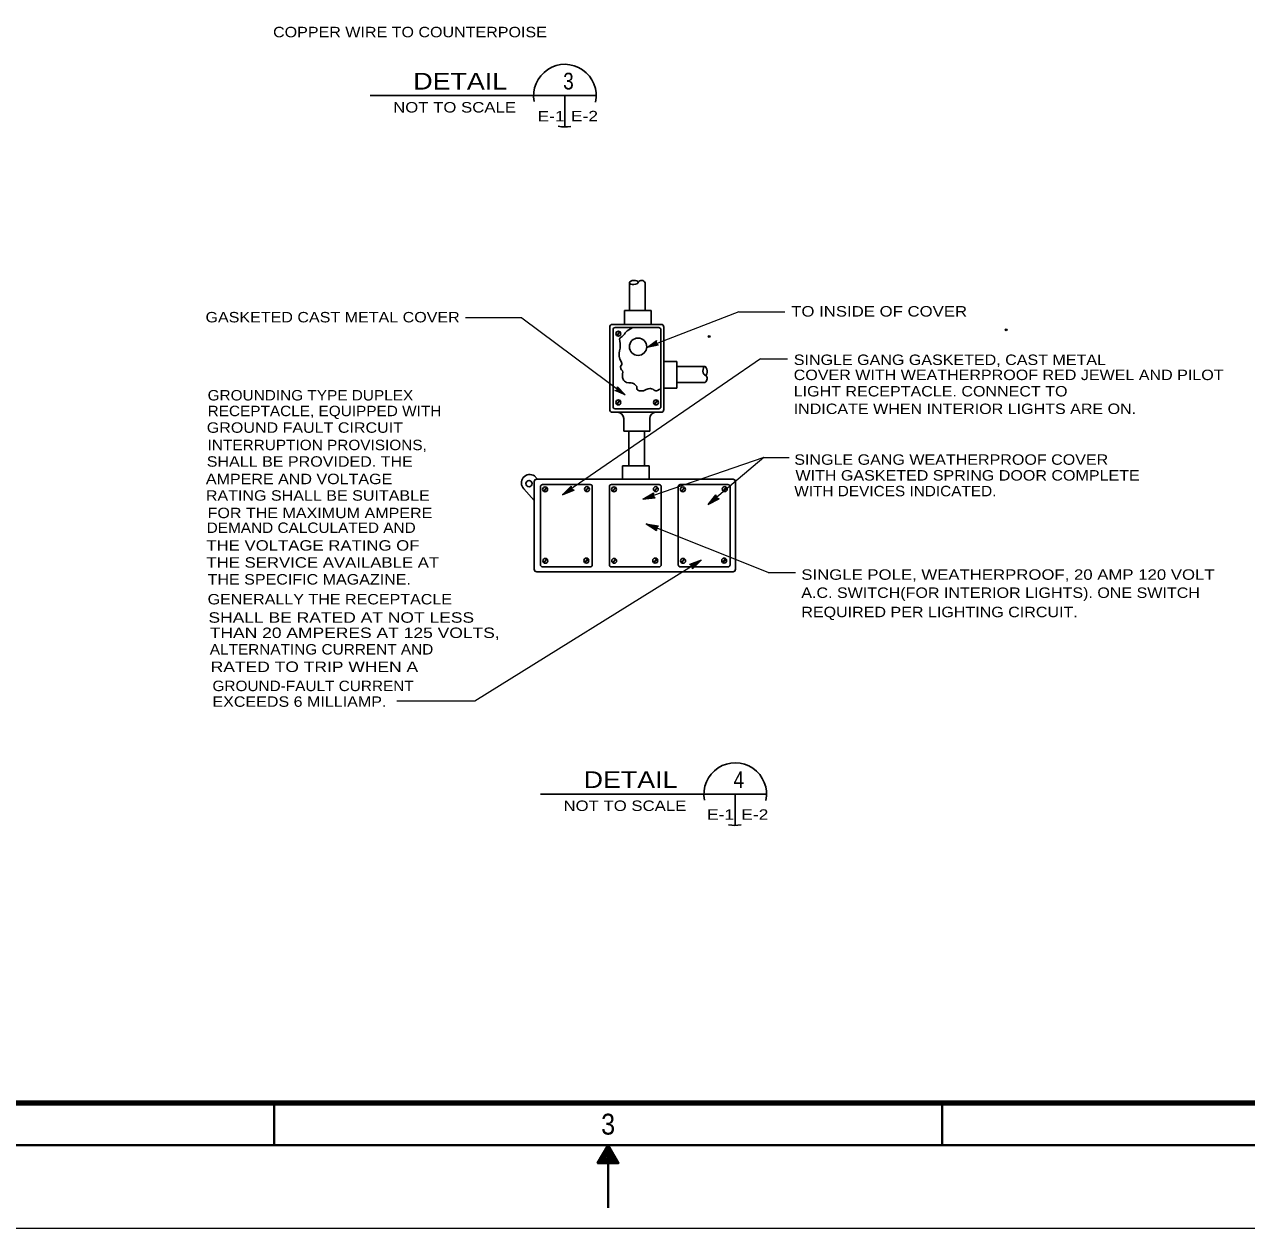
# Model space of a CAD drawing. Extents: x -39.6 to 16.1, y -17.6 to 34.
# Drawn here: x -11.89 to 2.75, y -17.59 to -3.17 of the extents above; entities that cross this region are included whole.
import ezdxf
from ezdxf.enums import TextEntityAlignment as Align

# ---------------------------------------------------------------- set-up
doc = ezdxf.new("R2010")
doc.units = 0
doc.header["$LTSCALE"] = 0.05
doc.header["$PDMODE"] = 32
doc.header["$PDSIZE"] = 0.025
doc.layers.add('1', color=7, linetype='Continuous', lineweight=13)

msp = doc.modelspace()

# ---------------------------------------------------------------- linework, layer by layer
at = {"layer": '1', "lineweight": 25}
for p, q in [((-7.74921, -4.02658), (-5.04021, -4.02658)), ((-5.41521, -4.02658), (-5.41521, -4.40158)), ((-4.64121, -6.60058), (-4.64121, -6.26658)), ((-4.45321, -6.60058), (-4.45321, -6.26658)), ((-4.70221, -6.76058), (-4.70221, -6.59958)), ((-4.38221, -6.59958), (-4.70221, -6.59958)), ((-4.38221, -6.76058), (-4.38221, -6.59958)), ((-4.87821, -6.80058), (-4.87821, -7.78258)), ((-4.26521, -6.76558), (-4.84321, -6.76558)), ((-4.83921, -6.82958), (-4.83921, -7.74958)), ((-4.29121, -6.80458), (-4.81421, -6.80458)), ((-4.75821, -6.85158), (-4.79821, -6.89558)), ((-4.75321, -6.85658), (-4.79321, -6.90058)), ((-4.26621, -6.82958), (-4.26621, -7.74958)), ((-4.23021, -6.80058), (-4.23021, -7.78258)), ((-4.23421, -7.21058), (-4.07321, -7.21058)), ((-4.07421, -7.27158), (-3.74021, -7.27158)), ((-4.07321, -7.53058), (-4.07321, -7.21058)), ((-4.07421, -7.45958), (-3.74021, -7.45958)), ((-4.23421, -7.53058), (-4.07321, -7.53058)), ((-4.75821, -7.67458), (-4.79821, -7.71858)), ((-4.75321, -7.67958), (-4.79321, -7.72358)), ((-4.30721, -7.67458), (-4.34721, -7.71858)), ((-4.30221, -7.67958), (-4.34221, -7.72358)), ((-4.26521, -7.81758), (-4.84321, -7.81758)), ((-4.29121, -7.77458), (-4.81421, -7.77458)), ((-4.71021, -7.89258), (-4.71021, -8.04258)), ((-4.39921, -7.89258), (-4.39921, -8.04258)), ((-4.39921, -8.04258), (-4.71021, -8.04258)), ((-4.65121, -8.45558), (-4.65121, -8.04258)), ((-4.46321, -8.45558), (-4.46321, -8.04258)), ((-4.72621, -8.61858), (-4.72621, -8.45758)), ((-4.72621, -8.45758), (-4.40621, -8.45758)), ((-4.72621, -8.61858), (-4.72621, -8.45758)), ((-4.40621, -8.45758), (-4.72621, -8.45758)), ((-4.40621, -8.61858), (-4.40621, -8.45758)), ((-4.40621, -8.61858), (-4.40621, -8.45758)), ((-5.74421, -8.61858), (-5.78621, -8.57258)), ((-5.75321, -8.61858), (-3.40221, -8.61858)), ((-5.78321, -8.87258), (-5.90821, -8.73458)), ((-5.78321, -9.69758), (-5.78321, -8.64858)), ((-5.70821, -9.64358), (-5.70821, -8.70858)), ((-5.68321, -8.68358), (-5.11221, -8.68358)), ((-5.67421, -8.76058), (-5.63421, -8.71658)), ((-5.66921, -8.76558), (-5.62921, -8.72158)), ((-5.17321, -8.75758), (-5.13321, -8.71358)), ((-5.16821, -8.76258), (-5.12821, -8.71858)), ((-5.08721, -9.64358), (-5.08721, -8.70858)), ((-4.88321, -9.64358), (-4.88321, -8.70858)), ((-4.85821, -8.68358), (-4.28721, -8.68358)), ((-4.84921, -8.76058), (-4.80921, -8.71658)), ((-4.84421, -8.76558), (-4.80421, -8.72158)), ((-4.34821, -8.75758), (-4.30821, -8.71358)), ((-4.34321, -8.76258), (-4.30321, -8.71858)), ((-4.26221, -9.64358), (-4.26221, -8.70858)), ((-4.05821, -9.64358), (-4.05821, -8.70858)), ((-4.03321, -8.68358), (-3.46221, -8.68358)), ((-4.02421, -8.76058), (-3.98421, -8.71658)), ((-4.01921, -8.76558), (-3.97921, -8.72158)), ((-3.52321, -8.75758), (-3.48321, -8.71358)), ((-3.51821, -8.76258), (-3.47821, -8.71858)), ((-3.43721, -9.64358), (-3.43721, -8.70858)), ((-3.37221, -9.69758), (-3.37221, -8.64858)), ((-5.67221, -9.61658), (-5.63221, -9.57258)), ((-5.66721, -9.62158), (-5.62721, -9.57758)), ((-5.18021, -9.61358), (-5.14021, -9.56958)), ((-5.17521, -9.61858), (-5.13521, -9.57458)), ((-4.84721, -9.61658), (-4.80721, -9.57258)), ((-4.84221, -9.62158), (-4.80221, -9.57758)), ((-4.35521, -9.61358), (-4.31521, -9.56958)), ((-4.35021, -9.61858), (-4.31021, -9.57458)), ((-4.02221, -9.61658), (-3.98221, -9.57258)), ((-4.01721, -9.62158), (-3.97721, -9.57758)), ((-3.53021, -9.61358), (-3.49021, -9.56958)), ((-3.52521, -9.61858), (-3.48521, -9.57458)), ((-5.75321, -9.72758), (-3.40221, -9.72758)), ((-5.68321, -9.66858), (-5.11221, -9.66858)), ((-4.85821, -9.66858), (-4.28721, -9.66858)), ((-4.03321, -9.66858), (-3.46221, -9.66858)), ((-5.70921, -12.38958), (-3.00021, -12.38958)), ((-3.37521, -12.38958), (-3.37521, -12.76458))]:
    msp.add_line(p, q, dxfattribs=at)
at = {"layer": '1'}
for p, q in [((-5.93021, -6.68658), (-6.60421, -6.68658)), ((-3.33221, -6.61658), (-4.42521, -7.03858)), ((-3.33221, -6.61658), (-2.78021, -6.61658)), ((-0.13521, -6.83258), (-0.13021, -6.83058)), ((-0.13521, -6.83258), (-0.13021, -6.83258)), ((-0.13421, -6.83258), (-0.13121, -6.83058)), ((-0.13421, -6.83258), (-0.13021, -6.83158)), ((-4.42521, -7.03858), (-4.31821, -6.95858)), ((-4.42521, -7.03858), (-4.29521, -7.01058)), ((-4.39821, -7.02658), (-4.32621, -6.97758)), ((-4.39821, -7.02658), (-4.31421, -7.00458)), ((-3.69121, -6.91058), (-3.68621, -6.90858)), ((-3.69121, -6.91058), (-3.68621, -6.91058)), ((-3.69021, -6.91058), (-3.68721, -6.90858)), ((-3.69021, -6.91058), (-3.68621, -6.90958)), ((-3.07221, -7.17958), (-5.44221, -8.80758)), ((-3.07221, -7.17958), (-2.74921, -7.17958)), ((-4.71921, -7.59258), (-4.79921, -7.55458)), ((-4.69421, -7.61058), (-4.78421, -7.51158)), ((-4.71921, -7.59258), (-4.78121, -7.53358)), ((-3.03121, -8.35858), (-4.48121, -8.85958)), ((-3.03121, -8.35858), (-3.69921, -8.92158)), ((-3.03121, -8.35858), (-2.72821, -8.35858)), ((-5.44221, -8.80758), (-5.34121, -8.70058)), ((-5.44221, -8.80758), (-5.30621, -8.75158)), ((-5.41221, -8.78658), (-5.34521, -8.71658)), ((-5.41221, -8.78658), (-5.32321, -8.74958)), ((-5.38221, -8.76658), (-5.35021, -8.73258)), ((-5.38221, -8.76658), (-5.34021, -8.74858)), ((-5.35021, -8.73258), (-5.34821, -8.74258)), ((-5.34821, -8.74258), (-5.34021, -8.74858)), ((-5.34521, -8.71658), (-5.34121, -8.73858)), ((-5.34121, -8.73858), (-5.32321, -8.74958)), ((-4.48121, -8.85958), (-4.35521, -8.78358)), ((-4.48121, -8.85958), (-4.33521, -8.84158)), ((-4.44621, -8.84758), (-4.36421, -8.79758)), ((-4.44621, -8.84758), (-4.35121, -8.83558)), ((-4.41221, -8.83558), (-4.37321, -8.81158)), ((-4.41221, -8.83558), (-4.36721, -8.82958)), ((-4.37321, -8.81158), (-4.37321, -8.82258)), ((-4.37321, -8.82258), (-4.36721, -8.82958)), ((-4.36421, -8.79758), (-4.36621, -8.81958)), ((-4.36621, -8.81958), (-4.35121, -8.83558)), ((-3.69921, -8.92158), (-3.60921, -8.80458)), ((-3.69921, -8.92158), (-3.56921, -8.85258)), ((-3.67121, -8.89758), (-3.61221, -8.82158)), ((-3.67121, -8.89758), (-3.58621, -8.85258)), ((-3.64321, -8.87458), (-3.61521, -8.83758)), ((-3.64321, -8.87458), (-3.60321, -8.85258)), ((-3.61521, -8.83758), (-3.61221, -8.84858)), ((-3.61221, -8.82158), (-3.60621, -8.84258)), ((-3.61221, -8.84858), (-3.60321, -8.85258)), ((-3.60621, -8.84258), (-3.58621, -8.85258)), ((-2.97921, -9.73558), (-4.44021, -9.15158)), ((-4.44021, -9.15158), (-4.29521, -9.17658)), ((-4.44021, -9.15158), (-4.31821, -9.23358)), ((-4.40621, -9.16558), (-4.31121, -9.18158)), ((-4.40621, -9.16558), (-4.32621, -9.21858)), ((-4.37221, -9.17858), (-4.33421, -9.20358)), ((-4.37221, -9.17858), (-4.32721, -9.18658)), ((-4.32721, -9.18658), (-4.33421, -9.19358)), ((-4.33421, -9.19358), (-4.33421, -9.20358)), ((-4.31121, -9.18158), (-4.32721, -9.19658)), ((-4.32721, -9.19658), (-4.32621, -9.21858)), ((-6.49221, -11.27458), (-3.78221, -9.58958)), ((-3.78221, -9.58958), (-3.92121, -9.63958)), ((-3.81321, -9.60958), (-3.90421, -9.64158)), ((-3.88621, -9.65358), (-3.90421, -9.64158)), ((-3.78221, -9.58958), (-3.88821, -9.69158)), ((-3.84421, -9.62858), (-3.88721, -9.64458)), ((-3.87921, -9.64958), (-3.88721, -9.64458)), ((-3.88321, -9.67558), (-3.88621, -9.65358)), ((-3.81321, -9.60958), (-3.88321, -9.67558)), ((-3.87721, -9.66058), (-3.87921, -9.64958)), ((-3.84421, -9.62858), (-3.87721, -9.66058)), ((-2.97921, -9.73558), (-2.65421, -9.73558)), ((-7.42821, -11.27458), (-6.49221, -11.27458)), ((16.10179, -17.59158), (-25.89821, -17.59158))]:
    msp.add_line(p, q, dxfattribs=at)
at = {"layer": '1', "lineweight": 40}
for p, q in [((-8.89821, -16.09158), (-8.89821, -16.59158)), ((-0.89821, -16.09158), (-0.89821, -16.59158)), ((-4.89821, -16.59158), (-4.89821, -17.34158))]:
    msp.add_line(p, q, dxfattribs=at)
for points in [[(-24.89821, -16.59158), (-24.89821, 11.40842), (15.10179, 11.40842), (15.10179, -16.59158)], [(-4.89821, -16.59158), (-4.77321, -16.80858), (-5.02321, -16.80858)]]:
    msp.add_lwpolyline(points, close=True, dxfattribs=at)
at = {"layer": '1', "lineweight": 90}
msp.add_lwpolyline([(-23.39821, 10.90842), (14.60179, 10.90842), (14.60179, -16.09158), (-23.39821, -16.09158)], close=True, dxfattribs=at)
at = {"layer": '1'}
for points in [[(-5.93021, -6.68658), (-4.69421, -7.61058), (-4.81721, -7.55658)], [(-0.13121, -6.83158), (-0.13221, -6.83158), (-0.13121, -6.83158)], [(-3.68721, -6.90958), (-3.68821, -6.90958), (-3.68721, -6.90958)], [(-5.34121, -8.70058), (-5.33521, -8.73358), (-5.30621, -8.75158)], [(-4.35521, -8.78358), (-4.35821, -8.81758), (-4.33521, -8.84158)], [(-3.60921, -8.80458), (-3.60021, -8.83758), (-3.56921, -8.85258)], [(-4.29521, -9.17658), (-4.31921, -9.19958), (-4.31821, -9.23358)], [(-3.88821, -9.69158), (-3.89221, -9.65858), (-3.92121, -9.63958)]]:
    msp.add_lwpolyline(points, dxfattribs=at)
at = {"layer": '1', "lineweight": 25}
msp.add_lwpolyline([(-4.26621, -7.54458), (-4.27721, -7.54158), (-4.28721, -7.54458), (-4.30621, -7.55558), (-4.31721, -7.55958), (-4.32721, -7.56058), (-4.33721, -7.55658), (-4.34621, -7.55358), (-4.35521, -7.54458), (-4.35921, -7.54458), (-4.36421, -7.54158), (-4.37721, -7.53558), (-4.38921, -7.53358), (-4.39921, -7.53358), (-4.41821, -7.53858), (-4.44021, -7.54558), (-4.45721, -7.55358), (-4.47321, -7.55958), (-4.49721, -7.56258), (-4.52021, -7.56058), (-4.53421, -7.55558), (-4.54421, -7.54858), (-4.54821, -7.54558), (-4.55221, -7.53158), (-4.55521, -7.50958), (-4.58221, -7.47958), (-4.59321, -7.47358), (-4.60421, -7.46958), (-4.62221, -7.46558), (-4.65121, -7.46458), (-4.67721, -7.46158), (-4.70221, -7.44458), (-4.71321, -7.43258), (-4.72621, -7.40058), (-4.72721, -7.37758), (-4.72421, -7.35558), (-4.72321, -7.33858), (-4.72621, -7.32258), (-4.73721, -7.30858), (-4.74421, -7.29858), (-4.74821, -7.26958), (-4.73521, -7.24458), (-4.73521, -7.23258), (-4.74121, -7.21158), (-4.75621, -7.18258), (-4.76721, -7.14558), (-4.76721, -7.10858), (-4.76321, -7.08258), (-4.75321, -7.05058), (-4.75221, -7.02958), (-4.75321, -6.99558), (-4.75921, -6.96758), (-4.76021, -6.94258), (-4.75321, -6.92758), (-4.73021, -6.90858), (-4.70221, -6.88058), (-4.69321, -6.86458), (-4.66821, -6.84458), (-4.62921, -6.81758), (-4.60321, -6.80458), (-4.60421, -6.80458)], dxfattribs=at)
at = {"layer": '1'}
for points in [[(-4.33421, -6.99858), (-4.33521, -7.00358), (-4.35921, -7.00958), (-4.33821, -6.99358)], [(-4.77621, -7.55458), (-4.77321, -7.54958), (-4.75421, -7.57058), (-4.77821, -7.55958)]]:
    msp.add_lwpolyline(points, close=True, dxfattribs=at)
at = {"layer": '1', "lineweight": 40}
for points in [[(-4.89721, -16.63458), (-4.80821, -16.78758), (-4.98621, -16.78758), (-4.89821, -16.63558)], [(-4.89821, -16.67358), (-4.84521, -16.76658), (-4.95021, -16.76658), (-4.89621, -16.67358)], [(-4.89821, -16.71658), (-4.88121, -16.74558), (-4.91421, -16.74558), (-4.89921, -16.71958)]]:
    msp.add_lwpolyline(points, dxfattribs=at)
at = {"layer": '1', "lineweight": 25}
for centre, radius in [((-4.77521, -6.87658), 0.02973), ((-4.53921, -7.03358), 0.10402), ((-4.77521, -7.69958), 0.02973), ((-4.32421, -7.69958), 0.02973), ((-5.84421, -8.67158), 0.03766), ((-5.65221, -8.74058), 0.02973), ((-5.15121, -8.73758), 0.02973), ((-4.82721, -8.74058), 0.02973), ((-4.32621, -8.73758), 0.02973), ((-4.00221, -8.74058), 0.02973), ((-3.50121, -8.73758), 0.02973), ((-5.65021, -9.59658), 0.02973), ((-5.15821, -9.59358), 0.02973), ((-4.82521, -9.59658), 0.02973), ((-4.33321, -9.59358), 0.02973), ((-4.00021, -9.59658), 0.02973), ((-3.50821, -9.59358), 0.02973)]:
    msp.add_circle(centre, radius, dxfattribs=at)
for centre, radius, start, end in [((-5.41521, -4.02658), 0.375, 348.02387, 190.92017), ((-5.41521, -4.02658), 0.375, 257.81974, 280.71312), ((-4.49786, -6.28722), 0.04919, 24.80309, 147.21509), ((-4.84321, -6.80058), 0.035, 90, 180), ((-4.81421, -6.82958), 0.025, 90, 180), ((-4.29121, -6.82958), 0.025, 0, 90), ((-4.26521, -6.80058), 0.035, 0, 90), ((-3.76084, -7.41493), 0.04919, 294.80309, 57.21509), ((-4.81421, -7.74958), 0.025, 180, 270), ((-4.29121, -7.74958), 0.025, 270, 0), ((-4.84321, -7.78258), 0.035, 180, 270), ((-4.78521, -7.89258), 0.075, 0, 90), ((-4.32421, -7.89258), 0.075, 90, 180), ((-4.26521, -7.78258), 0.035, 270, 0), ((-5.83597, -8.66406), 0.10095, 55.78574, 224.31098), ((-5.75321, -8.64858), 0.03, 90, 180), ((-3.40221, -8.64858), 0.03, 0, 90), ((-5.68321, -8.70858), 0.025, 90, 180), ((-5.11221, -8.70858), 0.025, 0, 90), ((-4.85821, -8.70858), 0.025, 90, 180), ((-4.28721, -8.70858), 0.025, 0, 90), ((-4.03321, -8.70858), 0.025, 90, 180), ((-3.46221, -8.70858), 0.025, 0, 90), ((-5.68321, -9.64358), 0.025, 180, 270), ((-5.11221, -9.64358), 0.025, 270, 0), ((-4.85821, -9.64358), 0.025, 180, 270), ((-4.28721, -9.64358), 0.025, 270, 0), ((-4.03321, -9.64358), 0.025, 180, 270), ((-3.46221, -9.64358), 0.025, 270, 0), ((-5.75321, -9.69758), 0.03, 180, 270), ((-3.40221, -9.69758), 0.03, 270, 0), ((-3.37521, -12.38958), 0.375, 348.02387, 190.92017), ((-3.37521, -12.38958), 0.375, 257.81974, 280.71312)]:
    msp.add_arc(centre, radius, start, end, dxfattribs=at)
at = {"layer": '1'}
for centre, radius, start, end in [((-0.13031, -6.83135), 0.000723, 141.09678, 247.11924), ((-0.12934, -6.83111), 0.00144, 141.03753, 247.17851), ((-4.30988, -6.98658), 0.01808, 151.09678, 257.11924), ((-4.28688, -6.97629), 0.03608, 151.03753, 257.17851), ((-3.68631, -6.90935), 0.000723, 141.09678, 247.11924), ((-3.68534, -6.90911), 0.00144, 141.03753, 247.17851), ((-4.81915, -7.52218), 0.03608, 271.27268, 17.41366), ((-4.79868, -7.53687), 0.01808, 271.33193, 17.35438)]:
    msp.add_arc(centre, radius, start, end, dxfattribs=at)
at = {"layer": '1', "lineweight": 25}
for centre, major_axis in [((-4.59021, -6.26358), (0.051, 0.003)), ((-3.73721, -7.32258), (0.003, -0.051))]:
    msp.add_ellipse(centre, major_axis=major_axis, ratio=0.487925, dxfattribs=at)
at = {"layer": '1'}
for p in [(-0.13121, -6.83158), (-3.68721, -6.90958)]:
    msp.add_point(p, dxfattribs=at)

# ---------------------------------------------------------------- texts
for s, width, p in [('COPPER WIRE TO COUNTERPOISE', 1.15, (-8.91021, -3.32758)), ('TO INSIDE OF COVER', 1.2, (-2.70521, -6.67158)), ('GASKETED CAST METAL COVER', 1.15, (-9.71921, -6.74158)), ('SINGLE GANG GASKETED, CAST METAL', 1.15, (-2.67421, -7.25158)), ('COVER WITH WEATHERPROOF RED JEWEL AND PILOT', 1.15, (-2.67521, -7.43258)), ('GROUNDING TYPE DUPLEX', 1.1, (-9.69421, -7.67658)), ('LIGHT RECEPTACLE. CONNECT TO', 1.15, (-2.67521, -7.62858)), ('RECEPTACLE, EQUIPPED WITH', 1.1, (-9.69421, -7.86458)), ('INDICATE WHEN INTERIOR LIGHTS ARE ON.', 1.15, (-2.67521, -7.83858)), ('GROUND FAULT CIRCUIT', 1.15, (-9.70421, -8.06358)), ('INTERRUPTION PROVISIONS,', 1.1, (-9.69421, -8.27158)), ('SINGLE GANG WEATHERPROOF COVER', 1.15, (-2.66821, -8.44658)), ('SHALL BE PROVIDED. THE', 1.15, (-9.70421, -8.46958)), ('AMPERE AND VOLTAGE', 1.15, (-9.71521, -8.67858)), ('WITH GASKETED SPRING DOOR COMPLETE', 1.15, (-2.65421, -8.63558)), ('RATING SHALL BE SUITABLE', 1.15, (-9.71521, -8.87658)), ('WITH DEVICES INDICATED.', 1.1, (-2.66821, -8.82358)), ('FOR THE MAXIMUM AMPERE', 1.15, (-9.69421, -9.08558)), ('DEMAND CALCULATED AND', 1.1, (-9.70521, -9.26258)), ('THE VOLTAGE RATING OF', 1.2, (-9.70921, -9.47458)), ('THE SERVICE AVAILABLE AT', 1.2, (-9.70821, -9.67858)), ('THE SPECIFIC MAGAZINE.', 1.15, (-9.69421, -9.88058)), ('SINGLE POLE, WEATHERPROOF, 20 AMP 120 VOLT', 1.2, (-2.58421, -9.82358)), ('A.C. SWITCH(FOR INTERIOR LIGHTS). ONE SWITCH', 1.15, (-2.58421, -10.04058)), ('GENERALLY THE RECEPTACLE', 1.15, (-9.69421, -10.11858)), ('SHALL BE RATED AT NOT LESS', 1.25, (-9.68421, -10.33758)), ('REQUIRED PER LIGHTING CIRCUIT.', 1.15, (-2.58421, -10.27158)), ('THAN 20 AMPERES AT 125 VOLTS,', 1.25, (-9.66821, -10.52058)), ('ALTERNATING CURRENT AND', 1.1, (-9.66821, -10.71858)), ('RATED TO TRIP WHEN A', 1.25, (-9.65721, -10.92758)), ('GROUND-FAULT CURRENT', 1.1, (-9.63621, -11.15658)), ('EXCEEDS 6 MILLIAMP.', 1.15, (-9.63621, -11.34458))]:
    msp.add_text(s, height=0.125, dxfattribs=dict(at, width=width)).set_placement(p)
for s, height, width, p in [('DETAIL', 0.2, 1.2, (-6.66921, -3.95358)), ('3', 0.2, 0.85, (-5.37271, -3.95258)), ('E-1', 0.125, 1.25, (-5.58121, -4.33558)), ('E-2', 0.125, 1.25, (-5.18121, -4.33358)), ('DETAIL', 0.2, 1.2, (-4.62921, -12.31658)), ('4', 0.2, 0.85, (-3.33271, -12.31558)), ('E-1', 0.125, 1.25, (-3.55121, -12.69658)), ('E-2', 0.125, 1.25, (-3.14121, -12.69658)), ('3', 0.25, 0.9, (-4.89771, -16.46658))]:
    msp.add_text(s, height=height, dxfattribs=dict(at, width=width)).set_placement(p, align=Align.CENTER)
at = {"layer": '1', "width": 1.2}
for p in [(-6.00121, -4.22858), (-3.96121, -12.59158)]:
    msp.add_text('NOT TO SCALE', height=0.125, dxfattribs=at).set_placement(p, align=Align.RIGHT)

doc.saveas('drawing.dxf')
